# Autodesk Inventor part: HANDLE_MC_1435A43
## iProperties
Created: 2009-01
Part Number: HANDLE_MC_1435A43
Document SubType Name: Modeling
Designer: claivier
Material: Aluminum-6061
Norme de conversion: STEP AP214IS
Nom du fichier: HANDLE_MC_1435A43.STEP
Préprocesseur: SolidWorks 2008
Postprocesseur: Build: 344a, Release: 11 SP2 - Date: Fri 08/18/2006
Unités envoyées: INCHES
Incertitude: 1e-05
Author: claivier
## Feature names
1. Base1
